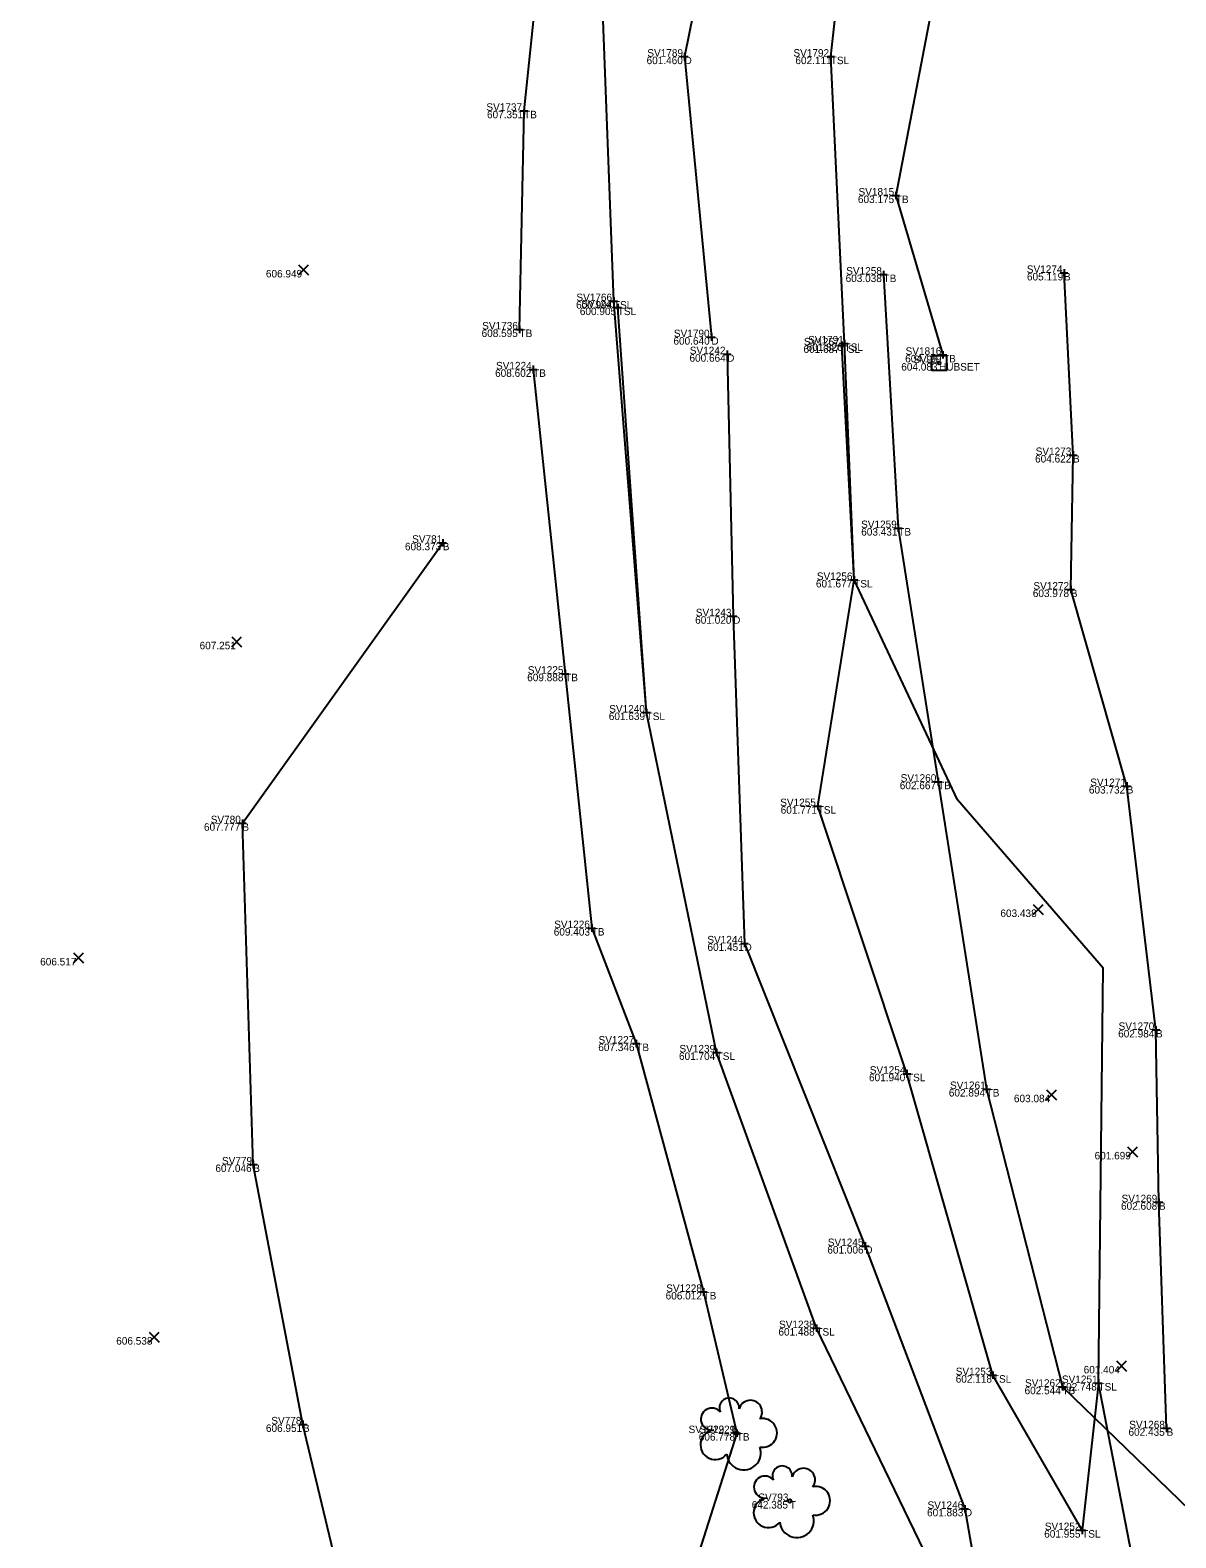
# Model space of a CAD drawing. Extents: x -2 to 1979875, y -2 to 232027.
# Drawn here: x 1978823.1 to 1978899.5, y 231361.9 to 231462.4 of the extents above; entities that cross this region are included whole.
import ezdxf

# ---------------------------------------------------------------- set-up
doc = ezdxf.new("R2010")
doc.units = 0
for name, color, linetype in [('_CIVIL_CONSTRUCTION', 7, 'Continuous'), ('DR_X_Ditch', 7, 'Continuous'), ('GE_P_Alignment', 7, 'Continuous'), ('GE_X_Alignment', 7, 'Continuous'), ('GE_X_Alignment_100_Curve_Data', 7, 'Continuous'), ('GE_X_Alignment_100_Stations', 7, 'Continuous'), ('HY_X_Water_Edge', 7, 'Continuous'), ('SV_P_Control_Cells_Set', 7, 'Continuous'), ('SV_X_Random_Point', 7, 'Continuous'), ('SV_X_Toe_of_Slope', 7, 'Continuous'), ('SV_X_Top_of_Bank', 7, 'Continuous'), ('VG_X_Cells', 7, 'Continuous')]:
    doc.layers.add(name, color=color, linetype=linetype)

msp = doc.modelspace()

# ---------------------------------------------------------------- linework, layer by layer
at = {"layer": 'DR_X_Ditch'}
for points in [[(1978962.19, 231606.29), (1978949.61, 231595.73), (1978937.1, 231586.52), (1978924.62, 231577.27), (1978916.58, 231558.51), (1978902.78, 231546.53), (1978893.02, 231523.59), (1978880.46, 231506.11), (1978875.72, 231493.26), (1978870.63, 231479.69), (1978866.76, 231460.62), (1978868.55, 231441.92)], [(1978869.6, 231440.78), (1978870, 231423.31), (1978870.76, 231401.5), (1978878.81, 231381.32), (1978885.45, 231363.8), (1978889.02, 231343.32), (1978889.73, 231326.13), (1978887.25, 231302.42)]]:
    msp.add_lwpolyline(points, dxfattribs=at)
at = {"layer": 'GE_P_Alignment'}
for points in [[(1978898.9, 231369.17), (1978898.39, 231384.24), (1978898.19, 231395.73), (1978896.24, 231411.99), (1978892.51, 231425.09), (1978892.66, 231434.06), (1978892.06, 231446.2)], [(1978805.08, 231302.9), (1978804.31, 231318.39), (1978807.02, 231337.48), (1978807.61, 231347.62), (1978815.87, 231349.44), (1978830.43, 231348.07), (1978839.19, 231344.01), (1978846.27, 231348.74), (1978841.32, 231369.43), (1978838.01, 231386.76), (1978837.28, 231409.51), (1978850.64, 231428.21)]]:
    msp.add_lwpolyline(points, dxfattribs=at)
at = {"layer": 'GE_X_Alignment_100_Curve_Data'}
for p, q in [((1978866.76, 231460.87), (1978866.76, 231460.37)), ((1978876.51, 231460.88), (1978876.51, 231460.38)), ((1978866.51, 231460.62), (1978867.01, 231460.62)), ((1978866.76, 231460.62), (1978866.76, 231460.62)), ((1978876.26, 231460.62), (1978876.76, 231460.62)), ((1978876.51, 231460.62), (1978876.51, 231460.62)), ((1978855.81, 231457.01), (1978856.31, 231457.01)), ((1978856.06, 231457.26), (1978856.06, 231456.76)), ((1978856.06, 231457.01), (1978856.06, 231457.01)), ((1978880.85, 231451.61), (1978880.85, 231451.11)), ((1978880.6, 231451.36), (1978881.1, 231451.36)), ((1978880.85, 231451.36), (1978880.85, 231451.36)), ((1978879.78, 231446.09), (1978880.28, 231446.09)), ((1978880.03, 231446.34), (1978880.03, 231445.84)), ((1978880.03, 231446.09), (1978880.03, 231446.09)), ((1978891.81, 231446.2), (1978892.31, 231446.2)), ((1978892.06, 231446.45), (1978892.06, 231445.95)), ((1978892.06, 231446.2), (1978892.06, 231446.2)), ((1978861.8, 231444.32), (1978862.3, 231444.32)), ((1978862.05, 231444.57), (1978862.05, 231444.07)), ((1978862.05, 231444.32), (1978862.05, 231444.32)), ((1978862.06, 231443.89), (1978862.56, 231443.89)), ((1978862.31, 231444.14), (1978862.31, 231443.64)), ((1978862.31, 231443.89), (1978862.31, 231443.89)), ((1978855.76, 231442.68), (1978855.76, 231442.18)), ((1978855.51, 231442.43), (1978856.01, 231442.43)), ((1978855.76, 231442.43), (1978855.76, 231442.43)), ((1978868.3, 231441.92), (1978868.8, 231441.92)), ((1978868.55, 231442.17), (1978868.55, 231441.67)), ((1978868.55, 231441.92), (1978868.55, 231441.92)), ((1978877.24, 231441.62), (1978877.24, 231441.12)), ((1978877.43, 231441.75), (1978877.43, 231441.25)), ((1978869.35, 231440.78), (1978869.85, 231440.78)), ((1978869.6, 231441.03), (1978869.6, 231440.53)), ((1978869.6, 231440.78), (1978869.6, 231440.78)), ((1978876.99, 231441.37), (1978877.49, 231441.37)), ((1978877.18, 231441.5), (1978877.68, 231441.5)), ((1978877.24, 231441.37), (1978877.24, 231441.37)), ((1978877.43, 231441.5), (1978877.43, 231441.5)), ((1978883.74, 231440.74), (1978884.24, 231440.74)), ((1978883.99, 231440.99), (1978883.99, 231440.49)), ((1978883.99, 231440.74), (1978883.99, 231440.74)), ((1978856.41, 231439.77), (1978856.91, 231439.77)), ((1978856.66, 231440.02), (1978856.66, 231439.52)), ((1978856.66, 231439.77), (1978856.66, 231439.77)), ((1978892.41, 231434.06), (1978892.91, 231434.06)), ((1978892.66, 231434.31), (1978892.66, 231433.81)), ((1978892.66, 231434.06), (1978892.66, 231434.06)), ((1978880.76, 231429.19), (1978881.26, 231429.19)), ((1978881.01, 231429.44), (1978881.01, 231428.94)), ((1978881.01, 231429.19), (1978881.01, 231429.19)), ((1978850.39, 231428.21), (1978850.89, 231428.21)), ((1978850.64, 231428.46), (1978850.64, 231427.96)), ((1978850.64, 231428.21), (1978850.64, 231428.21)), ((1978877.82, 231425.73), (1978878.32, 231425.73)), ((1978878.07, 231425.98), (1978878.07, 231425.48)), ((1978878.07, 231425.73), (1978878.07, 231425.73)), ((1978892.26, 231425.09), (1978892.76, 231425.09)), ((1978892.51, 231425.34), (1978892.51, 231424.84)), ((1978892.51, 231425.09), (1978892.51, 231425.09)), ((1978870, 231423.56), (1978870, 231423.06)), ((1978869.75, 231423.31), (1978870.25, 231423.31)), ((1978870, 231423.31), (1978870, 231423.31)), ((1978858.55, 231419.48), (1978859.05, 231419.48)), ((1978858.8, 231419.73), (1978858.8, 231419.23)), ((1978858.8, 231419.48), (1978858.8, 231419.48)), ((1978863.98, 231416.89), (1978864.48, 231416.89)), ((1978864.23, 231417.14), (1978864.23, 231416.64)), ((1978864.23, 231416.89), (1978864.23, 231416.89)), ((1978883.66, 231412.53), (1978883.66, 231412.03)), ((1978883.41, 231412.28), (1978883.91, 231412.28)), ((1978883.66, 231412.28), (1978883.66, 231412.28)), ((1978895.99, 231411.99), (1978896.49, 231411.99)), ((1978896.24, 231412.24), (1978896.24, 231411.74)), ((1978896.24, 231411.99), (1978896.24, 231411.99)), ((1978875.39, 231410.65), (1978875.89, 231410.65)), ((1978875.64, 231410.9), (1978875.64, 231410.4)), ((1978875.64, 231410.65), (1978875.64, 231410.65)), ((1978837.03, 231409.51), (1978837.53, 231409.51)), ((1978837.28, 231409.76), (1978837.28, 231409.26)), ((1978837.28, 231409.51), (1978837.28, 231409.51)), ((1978860.32, 231402.52), (1978860.82, 231402.52)), ((1978860.57, 231402.77), (1978860.57, 231402.27)), ((1978860.57, 231402.52), (1978860.57, 231402.52)), ((1978870.51, 231401.5), (1978871.01, 231401.5)), ((1978870.76, 231401.75), (1978870.76, 231401.25)), ((1978870.76, 231401.5), (1978870.76, 231401.5)), ((1978897.94, 231395.73), (1978898.44, 231395.73)), ((1978898.19, 231395.98), (1978898.19, 231395.48)), ((1978898.19, 231395.73), (1978898.19, 231395.73)), ((1978863.29, 231394.82), (1978863.79, 231394.82)), ((1978863.54, 231395.07), (1978863.54, 231394.57)), ((1978863.54, 231394.82), (1978863.54, 231394.82)), ((1978868.9, 231394.48), (1978868.9, 231393.98)), ((1978868.65, 231394.23), (1978869.15, 231394.23)), ((1978868.9, 231394.23), (1978868.9, 231394.23)), ((1978881.34, 231392.81), (1978881.84, 231392.81)), ((1978881.59, 231393.06), (1978881.59, 231392.56)), ((1978881.59, 231392.81), (1978881.59, 231392.81)), ((1978886.65, 231391.79), (1978887.15, 231391.79)), ((1978886.9, 231392.04), (1978886.9, 231391.54)), ((1978886.9, 231391.79), (1978886.9, 231391.79)), ((1978837.76, 231386.76), (1978838.26, 231386.76)), ((1978838.01, 231387.01), (1978838.01, 231386.51)), ((1978838.01, 231386.76), (1978838.01, 231386.76)), ((1978898.39, 231384.49), (1978898.39, 231383.99)), ((1978898.14, 231384.24), (1978898.64, 231384.24)), ((1978898.39, 231384.24), (1978898.39, 231384.24)), ((1978878.56, 231381.32), (1978879.06, 231381.32)), ((1978878.81, 231381.57), (1978878.81, 231381.07)), ((1978878.81, 231381.32), (1978878.81, 231381.32)), ((1978867.78, 231378.26), (1978868.28, 231378.26)), ((1978868.03, 231378.51), (1978868.03, 231378.01)), ((1978868.03, 231378.26), (1978868.03, 231378.26)), ((1978875.3, 231375.85), (1978875.8, 231375.85)), ((1978875.55, 231376.1), (1978875.55, 231375.6)), ((1978875.55, 231375.85), (1978875.55, 231375.85)), ((1978887.07, 231372.71), (1978887.57, 231372.71)), ((1978887.32, 231372.96), (1978887.32, 231372.46)), ((1978887.32, 231372.71), (1978887.32, 231372.71)), ((1978894.36, 231372.44), (1978894.36, 231371.94)), ((1978891.7, 231371.94), (1978892.2, 231371.94)), ((1978891.95, 231372.19), (1978891.95, 231371.69)), ((1978891.95, 231371.94), (1978891.95, 231371.94)), ((1978894.11, 231372.19), (1978894.61, 231372.19)), ((1978894.36, 231372.19), (1978894.36, 231372.19)), ((1978841.07, 231369.43), (1978841.57, 231369.43)), ((1978841.32, 231369.68), (1978841.32, 231369.18)), ((1978841.32, 231369.43), (1978841.32, 231369.43)), ((1978898.9, 231369.42), (1978898.9, 231368.92)), ((1978869.99, 231368.85), (1978870.49, 231368.85)), ((1978870.24, 231369.1), (1978870.24, 231368.6)), ((1978870.24, 231368.85), (1978870.24, 231368.85)), ((1978898.65, 231369.17), (1978899.15, 231369.17)), ((1978898.9, 231369.17), (1978898.9, 231369.17)), ((1978885.2, 231363.8), (1978885.7, 231363.8)), ((1978885.45, 231364.05), (1978885.45, 231363.55)), ((1978885.45, 231363.8), (1978885.45, 231363.8)), ((1978893.02, 231362.38), (1978893.52, 231362.38)), ((1978893.27, 231362.62), (1978893.27, 231362.12)), ((1978893.27, 231362.38), (1978893.27, 231362.38))]:
    msp.add_line(p, q, dxfattribs=at)
at = {"layer": 'HY_X_Water_Edge'}
for points in [[(1978903.08, 231327.23), (1978894.36, 231372.19), (1978894.66, 231399.85), (1978884.96, 231411.07), (1978878.07, 231425.73), (1978877.43, 231441.5), (1978876.51, 231460.62), (1978878.35, 231477.3), (1978884.08, 231491.84), (1978891.06, 231500.97), (1978902.06, 231518.22)], [(1978738.53, 231278.01), (1978757.26, 231280.76), (1978763.37, 231281.56), (1978784.16, 231284.04), (1978793.35, 231279.99), (1978807.7, 231286.51), (1978821.56, 231291.29), (1978840.75, 231297.53), (1978857.61, 231304.3), (1978872.97, 231309.55), (1978877.12, 231314.24), (1978883.49, 231319.37), (1978882.18, 231341.32), (1978883.05, 231360.36), (1978875.55, 231375.85), (1978868.9, 231394.23), (1978864.23, 231416.89), (1978862.05, 231444.32), (1978861.23, 231465.99)]]:
    msp.add_lwpolyline(points, dxfattribs=at)
at = {"layer": 'SV_P_Control_Cells_Set'}
msp.add_lwpolyline([(1978883.24, 231440.69), (1978884.23, 231440.69), (1978884.23, 231439.7), (1978883.24, 231439.7), (1978883.24, 231440.69)], dxfattribs=at)
msp.add_circle((1978883.73, 231440.19), 0.1, dxfattribs=at)
at = {"layer": 'SV_X_Random_Point'}
for p, q in [((1978841.03, 231446.07), (1978841.7, 231446.73)), ((1978841.03, 231446.73), (1978841.7, 231446.07)), ((1978836.57, 231421.27), (1978837.23, 231421.94)), ((1978836.57, 231421.94), (1978837.23, 231421.27)), ((1978890.01, 231403.42), (1978890.68, 231404.09)), ((1978890.01, 231404.09), (1978890.68, 231403.42)), ((1978826.02, 231400.2), (1978826.69, 231400.87)), ((1978826.02, 231400.87), (1978826.69, 231400.2)), ((1978890.9, 231391.08), (1978891.56, 231391.74)), ((1978890.9, 231391.74), (1978891.56, 231391.08)), ((1978896.29, 231387.27), (1978896.96, 231387.94)), ((1978896.29, 231387.94), (1978896.96, 231387.27)), ((1978831.06, 231374.92), (1978831.73, 231375.58)), ((1978831.06, 231375.58), (1978831.73, 231374.92)), ((1978895.56, 231372.99), (1978896.22, 231373.66)), ((1978895.56, 231373.66), (1978896.22, 231372.99))]:
    msp.add_line(p, q, dxfattribs=at)
at = {"layer": 'SV_X_Toe_of_Slope'}
for points in [[(1978862.05, 231444.32), (1978861.23, 231465.99), (1978863.73, 231474.53), (1978867.03, 231490.45), (1978874.95, 231511.66), (1978883.94, 231527.09), (1978886.49, 231533.36), (1978891.21, 231540.88), (1978905.93, 231559.12), (1978916.42, 231576.44), (1978923.02, 231585.21), (1978936.55, 231594.94), (1978953.84, 231610.59)], [(1978877.43, 231441.5), (1978876.51, 231460.62), (1978878.35, 231477.3), (1978884.08, 231491.84), (1978891.06, 231500.97), (1978902.06, 231518.22), (1978905.68, 231527.62), (1978917.18, 231541.58), (1978923.8, 231554.16), (1978935.08, 231565.85), (1978947.42, 231581.38), (1978957.98, 231589.89), (1978970.17, 231597.91)], [(1978883.49, 231319.37), (1978882.18, 231341.32), (1978883.05, 231360.36), (1978875.55, 231375.85), (1978868.9, 231394.23), (1978864.23, 231416.89), (1978862.31, 231443.89)], [(1978903.08, 231327.23), (1978894.36, 231372.19), (1978893.27, 231362.38), (1978887.32, 231372.71), (1978881.59, 231392.81), (1978875.64, 231410.65), (1978878.07, 231425.73), (1978877.24, 231441.37)]]:
    msp.add_lwpolyline(points, dxfattribs=at)
at = {"layer": 'SV_X_Top_of_Bank'}
for points in [[(1978855.76, 231442.43), (1978856.06, 231457.01), (1978857.9, 231474.54), (1978863.55, 231496.56), (1978873.07, 231519.31), (1978884.15, 231538.9), (1978898.65, 231557.24), (1978909.07, 231573.13), (1978911.03, 231578.63), (1978909.61, 231583.71), (1978914.7, 231591.39), (1978921.84, 231593.62), (1978928.84, 231591.83), (1978939.39, 231606.19)], [(1978970.43, 231596.93), (1978955.71, 231583.37), (1978942.85, 231568.03), (1978930.15, 231553.86), (1978923.45, 231536.94), (1978913.26, 231522.92), (1978902.63, 231500.51), (1978894.64, 231496.38), (1978887.78, 231488.62), (1978884.46, 231479.41), (1978883.35, 231464.48), (1978880.85, 231451.36), (1978883.99, 231440.74)], [(1978880.03, 231446.09), (1978881.01, 231429.19), (1978883.66, 231412.28), (1978886.9, 231391.79), (1978891.95, 231371.94), (1978902.57, 231361.66), (1978904.31, 231346.08), (1978905.4, 231330.39), (1978906.04, 231307.76), (1978904.66, 231298.81)], [(1978856.66, 231439.77), (1978858.8, 231419.48), (1978860.57, 231402.52), (1978863.54, 231394.82), (1978868.03, 231378.26), (1978870.24, 231368.85), (1978864.23, 231349.93), (1978865.3, 231335.11)]]:
    msp.add_lwpolyline(points, dxfattribs=at)
at = {"layer": 'VG_X_Cells'}
for centre in [(1978870.24, 231368.85), (1978873.77, 231364.32)]:
    msp.add_circle(centre, 0.12, dxfattribs=at)
for centre, radius, start, end in [((1978868.58, 231369.78), 0.735, 39.0625, 279.5412), ((1978869.75, 231370.53), 0.658, 354.0047, 205.9741), ((1978871.15, 231370.26), 0.776, 323.83, 165.0376), ((1978871.97, 231368.86), 0.957, 259.1453, 101.4596), ((1978868.81, 231368.07), 0.987, 96.1722, 320.5737), ((1978870.71, 231367.54), 1.14, 184.9476, 19.4572), ((1978873.28, 231366), 0.658, 354.0047, 205.9741), ((1978874.69, 231365.73), 0.776, 323.83, 165.0376), ((1978872.12, 231365.25), 0.735, 39.0625, 279.5412), ((1978875.51, 231364.34), 0.957, 259.1453, 101.4596), ((1978872.35, 231363.54), 0.987, 96.1722, 320.5737), ((1978874.25, 231363.02), 1.14, 184.9476, 19.4572)]:
    msp.add_arc(centre, radius, start, end, dxfattribs=at)

# ---------------------------------------------------------------- texts
at = {"layer": '_CIVIL_CONSTRUCTION'}
for s, p in [('601.460', (1978864.23, 231460.12)), ('602.111', (1978874.15, 231460.12)), ('607.351', (1978853.59, 231456.51)), ('603.175', (1978878.32, 231450.86)), ('606.949', (1978838.85, 231445.9)), ('603.038', (1978877.5, 231445.59)), ('605.119', (1978889.59, 231445.7)), ('600.994', (1978859.53, 231443.82)), ('600.905', (1978859.78, 231443.39)), ('608.595', (1978853.23, 231441.93)), ('600.640', (1978866.02, 231441.42)), ('600.664', (1978867.09, 231440.28)), ('601.687', (1978874.69, 231440.87)), ('601.820', (1978874.9, 231441)), ('604.109', (1978881.47, 231440.24)), ('608.602', (1978854.13, 231439.27)), ('604.083', (1978881.21, 231439.69)), ('604.622', (1978890.13, 231433.56)), ('603.431', (1978878.54, 231428.69)), ('608.373', (1978848.12, 231427.71)), ('601.677', (1978875.52, 231425.23)), ('603.978', (1978889.98, 231424.59)), ('601.020', (1978867.47, 231422.81)), ('607.251', (1978834.43, 231421.11)), ('609.888', (1978856.27, 231418.98)), ('601.639', (1978861.71, 231416.39)), ('602.667', (1978881.11, 231411.78)), ('603.732', (1978893.72, 231411.49)), ('601.771', (1978873.17, 231410.15)), ('607.777', (1978834.72, 231409.01)), ('603.438', (1978887.82, 231403.26)), ('609.403', (1978858.04, 231402.02)), ('601.451', (1978868.29, 231401)), ('606.517', (1978823.8, 231400.03)), ('602.984', (1978895.67, 231395.23)), ('607.346', (1978861.01, 231394.32)), ('601.704', (1978866.39, 231393.73)), ('601.940', (1978879.06, 231392.31)), ('602.894', (1978884.38, 231391.29)), ('603.084', (1978888.72, 231390.91)), ('601.699', (1978894.1, 231387.1)), ('607.046', (1978835.48, 231386.26)), ('602.608', (1978895.86, 231383.74)), ('601.006', (1978876.28, 231380.82)), ('606.012', (1978865.5, 231377.76)), ('606.538', (1978828.87, 231374.75)), ('601.488', (1978873.02, 231375.35)), ('601.404', (1978893.37, 231372.83)), ('602.118', (1978884.84, 231372.21)), ('602.748', (1978891.83, 231371.69)), ('602.544', (1978889.43, 231371.44)), ('606.951', (1978838.85, 231368.93)), ('606.778', (1978867.71, 231368.35)), ('606.778', (1978867.71, 231368.35)), ('602.435', (1978896.36, 231368.67)), ('642.385', (1978871.24, 231363.82)), ('601.883', (1978882.93, 231363.3)), ('601.955', (1978890.74, 231361.88))]:
    msp.add_text(s, height=0.5, dxfattribs=at).set_placement(p)
at = {"layer": 'GE_X_Alignment'}
for s, p in [('SV1789', (1978864.28, 231460.62)), ('SV1792', (1978874.02, 231460.62)), ('SV1737', (1978853.55, 231457.01)), ('SV1815', (1978878.36, 231451.36)), ('SV1258', (1978877.54, 231446.09)), ('SV1274', (1978889.58, 231446.2)), ('SV1766', (1978859.55, 231444.32)), ('SV1241', (1978859.88, 231443.89)), ('SV1736', (1978853.27, 231442.43)), ('SV1790', (1978866.05, 231441.92)), ('SV1257', (1978874.72, 231441.37)), ('SV1791', (1978875, 231441.5)), ('SV1242', (1978867.11, 231440.78)), ('SV1816', (1978881.5, 231440.74)), ('SV95', (1978882.01, 231440.19)), ('SV1224', (1978854.19, 231439.77)), ('SV1273', (1978890.17, 231434.06)), ('SV1259', (1978878.53, 231429.19)), ('SV781', (1978848.6, 231428.21)), ('SV1256', (1978875.58, 231425.73)), ('SV1272', (1978890.02, 231425.09)), ('SV1243', (1978867.51, 231423.31)), ('SV1225', (1978856.31, 231419.48)), ('SV1240', (1978861.74, 231416.89)), ('SV1260', (1978881.17, 231412.28)), ('SV1271', (1978893.81, 231411.99)), ('SV1255', (1978873.14, 231410.65)), ('SV780', (1978835.17, 231409.51)), ('SV1226', (1978858.07, 231402.52)), ('SV1244', (1978868.28, 231401.5)), ('SV1227', (1978861.03, 231394.82)), ('SV1270', (1978895.7, 231395.73)), ('SV1239', (1978866.42, 231394.23)), ('SV1254', (1978879.11, 231392.81)), ('SV1261', (1978884.46, 231391.79)), ('SV779', (1978835.92, 231386.76)), ('SV1269', (1978895.9, 231384.24)), ('SV1245', (1978876.31, 231381.32)), ('SV1228', (1978865.54, 231378.26)), ('SV1238', (1978873.06, 231375.85)), ('SV1253', (1978884.84, 231372.71)), ('SV1262', (1978889.46, 231371.94)), ('SV1251', (1978891.92, 231372.19)), ('SV778', (1978839.21, 231369.43)), ('SV1229_1', (1978867.03, 231368.85)), ('SV1229', (1978867.76, 231368.85)), ('SV1268', (1978896.41, 231369.17)), ('SV793', (1978871.68, 231364.32)), ('SV1246', (1978882.96, 231363.8)), ('SV1252', (1978890.78, 231362.38))]:
    msp.add_text(s, height=0.5, dxfattribs=at).set_placement(p)
at = {"layer": 'GE_X_Alignment_100_Stations'}
for s, p in [('D', (1978866.76, 231460.12)), ('TSL', (1978876.51, 231460.12)), ('TB', (1978856.06, 231456.51)), ('TB', (1978880.85, 231450.86)), ('TB', (1978880.03, 231445.59)), ('B', (1978892.06, 231445.7)), ('TSL', (1978862.05, 231443.82)), ('TSL', (1978862.31, 231443.39)), ('TB', (1978855.76, 231441.93)), ('D', (1978868.55, 231441.42)), ('D', (1978869.6, 231440.28)), ('TSL', (1978877.24, 231440.87)), ('TSL', (1978877.43, 231441)), ('TB', (1978883.99, 231440.24)), ('TB', (1978856.66, 231439.27)), ('HUBSET', (1978883.73, 231439.69)), ('B', (1978892.66, 231433.56)), ('TB', (1978881.01, 231428.69)), ('B', (1978850.64, 231427.71)), ('TSL', (1978878.07, 231425.23)), ('B', (1978892.51, 231424.59)), ('D', (1978870, 231422.81)), ('TB', (1978858.8, 231418.98)), ('TSL', (1978864.23, 231416.39)), ('TB', (1978883.66, 231411.78)), ('B', (1978896.24, 231411.49)), ('TSL', (1978875.64, 231410.15)), ('B', (1978837.28, 231409.01)), ('TB', (1978860.57, 231402.02)), ('D', (1978870.76, 231401)), ('B', (1978898.19, 231395.23)), ('TB', (1978863.54, 231394.32)), ('TSL', (1978868.9, 231393.73)), ('TSL', (1978881.59, 231392.31)), ('TB', (1978886.9, 231391.29)), ('B', (1978838.01, 231386.26)), ('B', (1978898.39, 231383.74)), ('D', (1978878.81, 231380.82)), ('TB', (1978868.03, 231377.76)), ('TSL', (1978875.55, 231375.35)), ('TSL', (1978887.32, 231372.21)), ('TSL', (1978894.36, 231371.69)), ('TB', (1978891.95, 231371.44)), ('B', (1978841.32, 231368.93)), ('TB', (1978870.24, 231368.35)), ('T', (1978870.24, 231368.35)), ('B', (1978898.9, 231368.67)), ('T', (1978873.77, 231363.82)), ('D', (1978885.45, 231363.3)), ('TSL', (1978893.27, 231361.88))]:
    msp.add_text(s, height=0.5, dxfattribs=at).set_placement(p)

doc.saveas('drawing.dxf')
